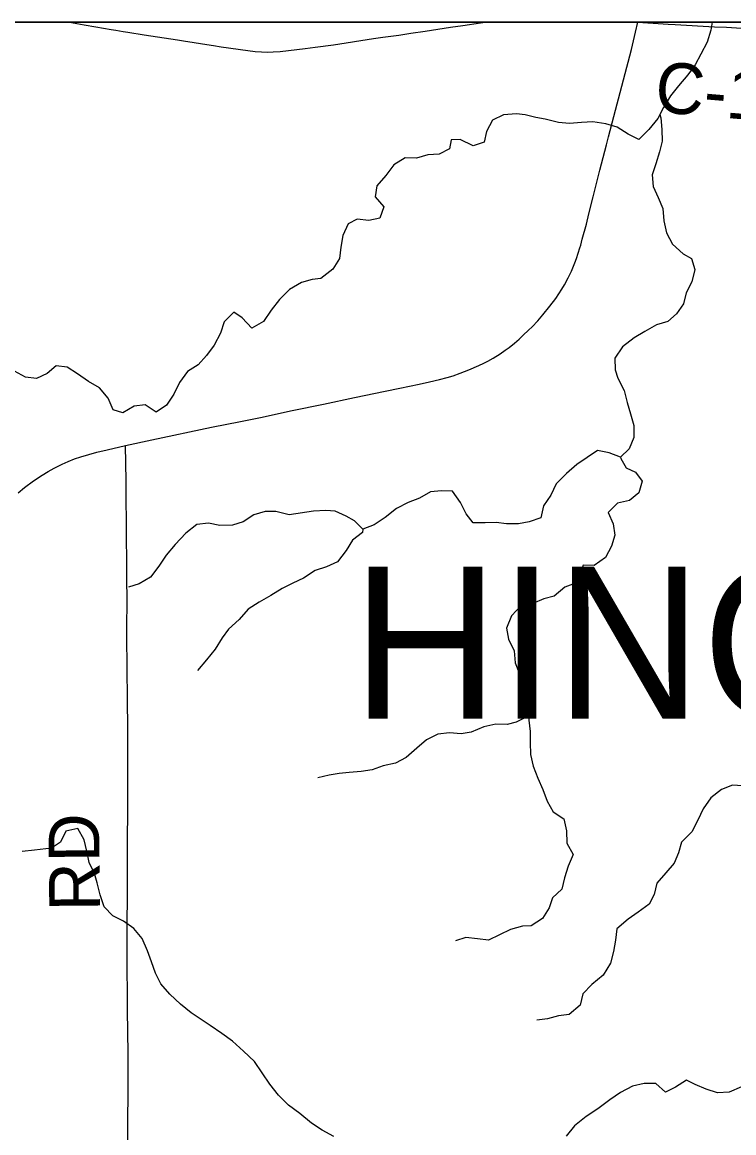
# Model space of a CAD drawing. Extents: x 0 to 34, y 0 to 22.
# Drawn here: x 5.297 to 6.095, y 19.655 to 20.9 of the extents above; entities that cross this region are included whole.
import ezdxf

# ---------------------------------------------------------------- set-up
doc = ezdxf.new("R2010")
doc.units = 0
for name, color, linetype in [('GM_X_Corporation', 7, 'Continuous'), ('GM_X_County_Road', 7, 'Continuous'), ('GM_X_County_Road_Text', 7, 'Continuous'), ('GM_X_Minor_River', 7, 'Continuous'), ('GM_X_State_Route', 7, 'Continuous'), ('GM_X_Township_Road', 7, 'Continuous'), ('GM_X_Township_Road_Text', 7, 'Continuous'), ('GM_X_Township_Text', 7, 'Continuous'), ('SH_Data', 7, 'Continuous')]:
    doc.layers.add(name, color=color, linetype=linetype)

msp = doc.modelspace()

# ---------------------------------------------------------------- linework, layer by layer
at = {"layer": 'GM_X_Corporation'}
msp.add_lwpolyline([(7.991, 17.7727), (7.9901, 18.1613), (7.988, 19.001), (7.9884, 19.0254), (7.9898, 19.1149), (7.9901, 19.6615), (7.9904, 20.2824), (7.9906, 20.6512), (7.9922, 20.9), (2.1, 20.9), (2.1, 14.1)], dxfattribs=at)
msp.add_lwpolyline([(7.9922, 20.9), (2.8099, 20.9), (2.8107, 20.774), (2.8158, 19.9868), (2.8247, 19.0323), (3.279, 19.0395), (3.3208, 19.0402), (3.8964, 19.0508), (4.1999, 19.0575), (4.5008, 19.0629), (4.7704, 19.0672), (4.9094, 19.0728), (5.4081, 19.0763), (6.7986, 19.0964), (7.9898, 19.1149), (7.9901, 19.6615), (7.9904, 20.2824), (7.9906, 20.6512)], close=True, dxfattribs=at)
at = {"layer": 'GM_X_County_Road'}
msp.add_lwpolyline([(5.9874, 20.8999), (6.0214, 20.8978), (6.0292, 20.8975), (6.0736, 20.8949), (6.0871, 20.8943), (6.1153, 20.8926), (6.1321, 20.8917), (6.155, 20.8899), (6.1936, 20.8859)], dxfattribs=at)
at = {"layer": 'GM_X_Minor_River'}
for points in [[(6.0708, 20.9), (6.0695, 20.8909), (6.0653, 20.8776), (6.0581, 20.8643), (6.0517, 20.8521), (6.0437, 20.841), (6.0331, 20.8285), (6.024, 20.8174), (6.0164, 20.8045), (6.0099, 20.7919), (5.9997, 20.7798), (5.9886, 20.7687), (5.9768, 20.7744), (5.9643, 20.7824), (5.9517, 20.7862), (5.9372, 20.7884), (5.9243, 20.7876), (5.911, 20.7865), (5.8984, 20.7876), (5.8836, 20.7914), (5.8733, 20.7933), (5.8611, 20.7963), (5.8516, 20.7974), (5.8368, 20.7963), (5.8246, 20.7902), (5.8178, 20.7776), (5.8151, 20.7655), (5.803, 20.7616), (5.7885, 20.7685), (5.7782, 20.7681), (5.7763, 20.7582), (5.7649, 20.7521), (5.752, 20.7513), (5.7394, 20.7475), (5.7265, 20.7478), (5.714, 20.7402), (5.7049, 20.728), (5.695, 20.7166), (5.6931, 20.7041), (5.7026, 20.6931), (5.6981, 20.6805), (5.6859, 20.6778), (5.673, 20.6793), (5.6627, 20.674), (5.6566, 20.661), (5.6547, 20.6477), (5.6529, 20.6352), (5.6456, 20.623), (5.6323, 20.6127), (5.6225, 20.6116), (5.6103, 20.6081), (5.597, 20.6005), (5.5856, 20.5891), (5.5765, 20.5773), (5.5677, 20.5647), (5.5548, 20.5571), (5.5441, 20.5685), (5.5346, 20.5749), (5.5236, 20.5643), (5.5198, 20.5513), (5.5126, 20.538), (5.5039, 20.5266), (5.4947, 20.5159), (5.4826, 20.5083), (5.4738, 20.4961), (5.4674, 20.4832), (5.459, 20.4706), (5.4476, 20.463), (5.4351, 20.471), (5.4229, 20.4698), (5.41, 20.4622), (5.3993, 20.4656), (5.3936, 20.4785), (5.3841, 20.4903), (5.3715, 20.4972), (5.3593, 20.5059), (5.3479, 20.5135), (5.3353, 20.515), (5.3254, 20.5062), (5.3133, 20.5005), (5.3011, 20.502), (5.2885, 20.5088)], [(6.0123, 20.7965), (6.0133, 20.7927), (6.0145, 20.7798), (6.0149, 20.7668), (6.0119, 20.7547), (6.0077, 20.7414), (6.0035, 20.7288), (6.0047, 20.7159), (6.0104, 20.7037), (6.0154, 20.6912), (6.0166, 20.6775), (6.0196, 20.6638), (6.0265, 20.6512), (6.0383, 20.6402), (6.0478, 20.6353), (6.0513, 20.6227), (6.0479, 20.6091), (6.0418, 20.5965), (6.0388, 20.5843), (6.0308, 20.5733), (6.0213, 20.5645), (6.0084, 20.5607), (5.9954, 20.5535), (5.9833, 20.5462), (5.9703, 20.5363), (5.9616, 20.5234), (5.962, 20.5104), (5.9651, 20.5009), (5.9723, 20.4873), (5.9754, 20.4736), (5.9792, 20.461), (5.983, 20.4481), (5.983, 20.4344), (5.9777, 20.4218), (5.9682, 20.4123), (5.9553, 20.4173), (5.9424, 20.4199), (5.9306, 20.4119), (5.9192, 20.4043), (5.9074, 20.394), (5.896, 20.3826), (5.8899, 20.37), (5.8819, 20.3578), (5.8789, 20.3445), (5.8656, 20.3399), (5.8538, 20.3376), (5.8401, 20.3376), (5.8287, 20.3391), (5.8165, 20.3387), (5.8028, 20.3387), (5.7952, 20.349), (5.7887, 20.3615), (5.7796, 20.3744), (5.7674, 20.3748), (5.7552, 20.3737), (5.7427, 20.3664), (5.7301, 20.3618), (5.7168, 20.355), (5.7043, 20.3447), (5.6921, 20.3367), (5.6792, 20.3317), (5.67, 20.3412), (5.6605, 20.3465), (5.6483, 20.3518), (5.6377, 20.3526), (5.624, 20.3518), (5.5966, 20.348), (5.5817, 20.3514), (5.5696, 20.3514), (5.557, 20.3479), (5.5452, 20.3399), (5.5331, 20.3361), (5.519, 20.3357), (5.506, 20.3384), (5.4931, 20.3368), (5.4809, 20.3273), (5.4688, 20.3147), (5.4589, 20.3025), (5.4506, 20.2904), (5.4411, 20.2778), (5.4285, 20.2706), (5.4163, 20.2667)], [(5.9682, 20.4124), (5.9683, 20.4109), (5.9743, 20.4005), (5.985, 20.3956), (5.9922, 20.3854), (5.9885, 20.3724), (5.9782, 20.364), (5.9649, 20.361), (5.9542, 20.3503), (5.96, 20.3378), (5.9619, 20.3252), (5.9581, 20.3127), (5.9513, 20.3001), (5.9387, 20.291), (5.9262, 20.2913), (5.9228, 20.2807), (5.9178, 20.2712), (5.9057, 20.2666), (5.8939, 20.2567), (5.8821, 20.2536), (5.8699, 20.2483), (5.857, 20.2464), (5.846, 20.2346), (5.8403, 20.2209), (5.8426, 20.2083), (5.8487, 20.1954), (5.8499, 20.1821), (5.8548, 20.1695), (5.8613, 20.157), (5.864, 20.1429), (5.8652, 20.13), (5.8652, 20.1178), (5.8667, 20.1049), (5.8667, 20.0927), (5.8671, 20.0791), (5.8702, 20.0661), (5.8755, 20.0528), (5.8809, 20.0399), (5.8858, 20.027), (5.8927, 20.0148), (5.9045, 20.0072), (5.9076, 19.9935), (5.908, 19.9798), (5.9152, 19.9669), (5.9095, 19.954), (5.9054, 19.941), (5.9024, 19.9281), (5.8917, 19.9186), (5.8883, 19.9072), (5.8807, 19.8954), (5.8678, 19.887), (5.8583, 19.8866), (5.8446, 19.8832), (5.8202, 19.871), (5.8077, 19.8725), (5.7948, 19.874), (5.783, 19.8702)], [(5.6791, 20.3318), (5.6788, 20.3279), (5.6678, 20.3195), (5.6606, 20.3077), (5.6507, 20.2952), (5.6385, 20.2895), (5.6256, 20.2856), (5.6127, 20.2769), (5.6009, 20.2712), (5.5887, 20.2654), (5.5762, 20.2574), (5.5629, 20.2498), (5.5507, 20.2422), (5.5404, 20.2304), (5.5287, 20.2197), (5.5214, 20.2098), (5.5135, 20.1973), (5.504, 20.1851), (5.4937, 20.1733)], [(5.8652, 20.1224), (5.864, 20.1216), (5.8511, 20.1155), (5.8412, 20.1129), (5.8283, 20.1132), (5.815, 20.1102), (5.8005, 20.1041), (5.7895, 20.1022), (5.7765, 20.1033), (5.7632, 20.1021), (5.7507, 20.0956), (5.7397, 20.0861), (5.7279, 20.0758), (5.7157, 20.0694), (5.702, 20.0663), (5.6898, 20.0621), (5.6773, 20.0602), (5.664, 20.059), (5.6526, 20.0579), (5.6415, 20.056), (5.6286, 20.0529)], [(6.105, 20.044), (6.0936, 20.0447), (6.0814, 20.0401), (6.0692, 20.0306), (6.0609, 20.0181), (6.0548, 20.0055), (6.048, 19.9926), (6.0366, 19.9808), (6.0332, 19.969), (6.0283, 19.9572), (6.0191, 19.9465), (6.0089, 19.9351), (6.0059, 19.9222), (6.0002, 19.9115), (5.988, 19.9024), (5.9766, 19.8947), (5.9641, 19.8837), (5.9626, 19.8711), (5.9603, 19.8582), (5.9569, 19.8453), (5.9485, 19.832), (5.936, 19.8213), (5.9257, 19.811), (5.9227, 19.7981), (5.9105, 19.7878), (5.8984, 19.7863), (5.8862, 19.7828), (5.8744, 19.7813)], [(5.6467, 19.6509), (5.6337, 19.6581), (5.6215, 19.6661), (5.6086, 19.6768), (5.596, 19.6862), (5.5846, 19.6973), (5.5751, 19.7098), (5.5663, 19.7223), (5.5579, 19.7349), (5.5453, 19.7466), (5.5331, 19.758), (5.521, 19.7664), (5.508, 19.7755), (5.4981, 19.7823), (5.4867, 19.7895), (5.4749, 19.7994), (5.4627, 19.8104), (5.4528, 19.8222), (5.4467, 19.834), (5.4421, 19.8469), (5.4379, 19.8591), (5.4318, 19.8728), (5.4226, 19.8842), (5.4108, 19.8925), (5.399, 19.8982), (5.3891, 19.9085), (5.3849, 19.9218), (5.3814, 19.9354), (5.3784, 19.9457), (5.3723, 19.9583), (5.3696, 19.9708), (5.3669, 19.9837), (5.3597, 19.9963), (5.3463, 19.9932), (5.3403, 19.981), (5.33, 19.9742), (5.311, 19.9719), (5.2973, 19.9703)], [(6.1036, 19.7067), (6.0899, 19.7006), (6.077, 19.6998), (6.064, 19.7039), (6.0518, 19.7093), (6.0419, 19.7142), (6.0298, 19.7062), (6.0184, 19.7008), (6.0077, 19.7103), (5.9948, 19.7103), (5.9814, 19.7073), (5.9681, 19.7004), (5.956, 19.692), (5.9427, 19.6821), (5.9297, 19.6734), (5.9164, 19.6631), (5.9073, 19.6513)]]:
    msp.add_lwpolyline(points, dxfattribs=at)
at = {"layer": 'GM_X_State_Route'}
msp.add_line((5.9874, 20.8999), (5.9875, 20.9), dxfattribs=at)
for points in [[(5.4428, 20.4318), (5.5096, 20.446), (5.5421, 20.4525), (5.5643, 20.457), (5.5999, 20.4646), (5.635, 20.4719), (5.67, 20.4793), (5.7043, 20.4864), (5.7208, 20.4899), (5.7425, 20.4942), (5.7539, 20.4969), (5.7652, 20.4996), (5.7736, 20.5017), (5.7804, 20.5037), (5.7883, 20.5065), (5.7981, 20.5103), (5.8091, 20.5151), (5.8149, 20.5179), (5.8192, 20.5201), (5.8254, 20.5236), (5.8331, 20.5284), (5.8389, 20.5324), (5.8432, 20.5355), (5.8494, 20.5404), (5.8543, 20.5448), (5.859, 20.5492), (5.8651, 20.5547), (5.8689, 20.5584), (5.8753, 20.5653), (5.881, 20.5721), (5.8889, 20.5816), (5.8955, 20.5904), (5.8991, 20.5957), (5.9024, 20.6008), (5.9052, 20.6057), (5.9094, 20.6134), (5.913, 20.6208), (5.9169, 20.6301), (5.9189, 20.6353), (5.9208, 20.6413), (5.9226, 20.647), (5.9235, 20.6502), (5.9252, 20.6568), (5.9298, 20.6737), (5.9326, 20.6853), (5.9375, 20.7044), (5.945, 20.7341), (5.9523, 20.7624), (5.9547, 20.7717), (5.9607, 20.7942), (5.9803, 20.8693), (5.985, 20.889), (5.9874, 20.8999)], [(5.2928, 20.3725), (5.2997, 20.3784), (5.31, 20.3858), (5.3196, 20.3921), (5.3263, 20.3963), (5.3333, 20.4001), (5.3421, 20.4047), (5.3487, 20.4077), (5.3559, 20.4105), (5.3631, 20.4129), (5.3721, 20.4155), (5.3809, 20.4179), (5.3926, 20.4208), (5.4133, 20.4255), (5.4428, 20.4318)]]:
    msp.add_lwpolyline(points, dxfattribs=at)
at = {"layer": 'GM_X_Township_Road'}
for points in [[(5.3503, 20.9), (5.3667, 20.897), (5.3799, 20.8947), (5.3972, 20.8918), (5.4021, 20.891), (5.4104, 20.8896), (5.4158, 20.8888), (5.4339, 20.8859), (5.4716, 20.8801), (5.4782, 20.879), (5.5091, 20.8743), (5.5116, 20.8739), (5.5204, 20.8725), (5.5501, 20.8683), (5.5585, 20.8673), (5.5657, 20.8668), (5.5719, 20.8666), (5.5786, 20.8668), (5.5864, 20.8672), (5.6144, 20.8704), (5.6258, 20.8719), (5.6464, 20.8748), (5.691, 20.8817), (5.7016, 20.8831), (5.7197, 20.8856), (5.7329, 20.8876), (5.749, 20.8901), (5.7774, 20.8943), (5.7912, 20.8963), (5.8111, 20.8992), (5.8163, 20.9)], [(5.4163, 19.078), (5.4163, 19.1296), (5.4159, 19.6241), (5.4161, 19.744), (5.4154, 19.7926), (5.4151, 19.8575), (5.4158, 20.0466), (5.4156, 20.1042), (5.4153, 20.1449), (5.4151, 20.1718), (5.4148, 20.2161), (5.415, 20.2571), (5.4148, 20.2717), (5.4145, 20.3005), (5.4144, 20.3184), (5.4142, 20.3385), (5.4139, 20.3667), (5.4137, 20.3859), (5.4133, 20.4255)]]:
    msp.add_lwpolyline(points, dxfattribs=at)
at = {"layer": 'SH_Data'}
msp.add_line((2.1, 20.9), (8.9, 20.9), dxfattribs=at)

# ---------------------------------------------------------------- texts
at = {"layer": 'GM_X_County_Road_Text'}
msp.add_text('C-140', height=0.05682, rotation=355.1012, dxfattribs=at).set_placement((6.0053, 20.7997))
at = {"layer": 'GM_X_Township_Road_Text'}
msp.add_text('RD', height=0.05682, rotation=90.4937, dxfattribs=at).set_placement((5.3845, 19.9037))
at = {"layer": 'GM_X_Township_Text'}
msp.add_text('HINCKLEY', height=0.17045, rotation=0, dxfattribs=at).set_placement((5.667, 20.1193))

doc.saveas('drawing.dxf')
